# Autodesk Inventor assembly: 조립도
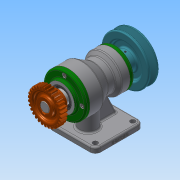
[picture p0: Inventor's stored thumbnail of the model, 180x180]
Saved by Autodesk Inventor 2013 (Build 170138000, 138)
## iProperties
Created: 2019-01
Part Number: 조립도
Document SubType Name: Assembly
Designer: Administrator
Author: Administrator
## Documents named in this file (15)
- C:\Users\Administrator\Desktop\490107V1013\조립도.iam
- C:\Users\Administrator\Desktop\490107V1013\본체.ipt
- C:\Users\Administrator\Desktop\490107V1013\축.ipt
- C:\Users\Administrator\Desktop\490107V1013\키 6 x 6 x 18.ipt
- C:\Users\Administrator\Desktop\490107V1013\키 5 x 5 x 20.ipt
- C:\Users\Administrator\Desktop\490107V1013\베어링 6203.ipt
- C:\Users\Administrator\Desktop\490107V1013\뒤커버.ipt
- C:\Users\Administrator\Desktop\490107V1013\볼트 M4.ipt
- C:\Users\Administrator\Desktop\490107V1013\오일 실 17 30 8.ipt
- C:\Users\Administrator\Desktop\490107V1013\베어링 6205.ipt
- C:\Users\Administrator\Desktop\490107V1013\앞커버.ipt
- C:\Users\Administrator\Desktop\490107V1013\오일 실 25 38 8.ipt
- C:\Users\Administrator\Desktop\490107V1013\스퍼기어.ipt
- C:\Users\Administrator\Desktop\490107V1013\멈춤나사 M3.ipt
- C:\Users\Administrator\Desktop\490107V1013\V-벨트풀리.ipt
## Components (1 placed, 1 different names)
1. V-벨트풀리:1 — 플러쉬:2
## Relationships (1: Flush 1)
- 플러쉬:2 [Flush]: V-벨트풀리:1
